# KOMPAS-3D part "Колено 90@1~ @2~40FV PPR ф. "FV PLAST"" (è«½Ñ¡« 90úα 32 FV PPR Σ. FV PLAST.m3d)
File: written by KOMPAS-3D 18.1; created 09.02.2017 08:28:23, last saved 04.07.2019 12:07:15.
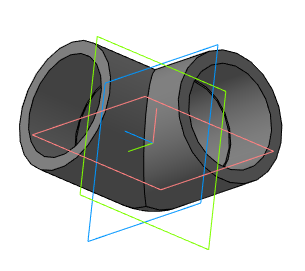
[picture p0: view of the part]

Document properties: Автор: Милов; Организация: Милов; Полное имя файла: D:\Magna\Магна Ins\Магна ins 10\М10-00.00.000\3Д\Колено 90гр 32 FV PPR ф. FV PLAST.m3d

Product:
- Part/product: Колено 90@1~ @2~40FV PPR ф. "FV PLAST"
    Масса: 0.141726
    Раздел спецификации: Прочие изделия
- Part/product: Колено ПВХ 32-90 PN16  | designation 01
    Масса: 0.0689411
    Раздел спецификации: Прочие изделия

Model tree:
1. Эскиз:1
2. Операция выдавливания:9
     Расстояние 1 = 34.2
3. Массив по концентрической сетке:1  (with: Операция выдавливания:9, Эскиз:1)  (2 pattern instances)
     Шаг 2 = 90
4. Эскиз:20  (with: Операция выдавливания:9)
5. Вырезать элемент выдавливания:6
     Расстояние 1 = 34.2
6. Эскиз:21  (with: Операция выдавливания:9)
7. Вырезать элемент выдавливания:7
     Расстояние 1 = 34.2
8. Эскиз:22  (with: Операция выдавливания:9)
9. Вырезать элемент выдавливания:8
     Расстояние 1 = 18.1
10. Массив по концентрической сетке:3  (with: Вырезать элемент выдавливания:8, Эскиз:22)  (2 pattern instances)
     Шаг 2 = 90
11. Эскиз:23  (with: Операция выдавливания:9, Вырезать элемент выдавливания:6)
12. Операция вращения:1
     Угол 1 = 90

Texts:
  Body Specification ( left align )
  Body Specificaton ( centered )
